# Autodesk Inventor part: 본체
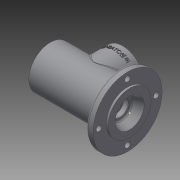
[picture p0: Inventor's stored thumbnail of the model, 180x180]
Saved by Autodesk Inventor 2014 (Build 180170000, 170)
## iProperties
Created: 2016-08
Part Number: 본체
Material: 일반
Document SubType Name: Modeling
Designer: USER
Density: 1 g/cm^3
Appearance: 기본값
Mass: 268.699 g
Surface Area: 614.616 cm^2
Volume: 268.699 cm^3
Author: USER
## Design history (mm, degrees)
sketch "스케치1"
  geometry: 1 further point
sketch "스케치2"
  geometry: L1 (-16.69, 0)-(0, 0); L2 (-115, 0)-(-115, 31); L3 (-115, 31)-(-13, 31); L4 (-13, 31)-(-13, 50); L5 (-13, 50)-(-3, 50); L6 (-3, 50)-(-3, 31); L7 (-3, 31)-(0, 31); L8 (0, 31)-(0, 0); L9 (0, 0)-(-115, 0)
  constraints: 18 end point, 4 parallel, 2 collinear, 2 perpendicular, 1 horizontal, 1 point on line
  dimensions: "d5" = 62 diameter of L3 L1; "d6" = 100 diameter of L5 L1; "d7" = 62 diameter of L7 L1; "d8" = 115 distance between parallel lines of L8 L2; "d9" = 102 distance of L2.end L3.end; "d10" = 10 distance of L4.end L5.end
revolve "회전1" sketch "스케치2" stored, may be unused: angle "d11" = 90 deg
node "작업 평면1"
sketch "스케치3"
  geometry: L1 (115, 31)-(115, -31) reference; C1 r 30 at (59, 0); 1 further point
  constraints: 1 centre point, 1 horizontal alignment
  dimensions: "d13" = 60 diameter of C1; "d14" = 56 distance from line of L1 C1.centre
extrude "돌출1" join sketch "스케치3" stored distance "d15" = 10; taper "d16" = 0 deg
sketch "스케치4" dims "d17" = 48
  geometry: C1 r 30 at (0, 0) reference; 3 further points
  constraints: 2 vertical alignment, 1 coincident, 2 other
hole "구멍1" sketch "스케치4" at (0, 24) diameter "d18" = 3.242; stored, may be unused: countersink angle "d22" = 90 deg, drill point angle "d24" = 118 deg; dims "d19" = 8, "d20" = 4, "d21" = 2, "d23" = 10
sketch "스케치7"
  geometry: C1 r 31 at (0, 0) reference; C2 r 21 at (0, 0)
  constraints: 1 centre point, 1 coincident
  dimensions: "d28" = 42 diameter of C2
extrude "돌출2" cut sketch "스케치7" distance "d29" = 9; taper "d30" = 0 deg
sketch "스케치9"
  geometry: C1 r 21 at (0, 0) reference; C2 r 24 at (0, 0)
  constraints: 1 centre point, 1 coincident
  dimensions: "d32" = 48 diameter of C2
extrude "돌출3" cut sketch "스케치9" distance "d33" = 3; taper "d34" = 0 deg
sketch "스케치10"
  geometry: C1 r 24 at (0, 0) reference; C2 r 20 at (0, 0)
  constraints: 1 centre point, 1 coincident
  dimensions: "d35" = 40 diameter of C2
extrude "돌출4" cut sketch "스케치10" distance "d36" = 9; taper "d37" = 0 deg
feature "스레드1" dims "d62" = 10, "d63" = 0
chamfer "모따기1" distance "d64" = 1; stored, may be unused: second distance "d65" = 2, angle "d66" = 45 deg
fillet "모깎기4" dims "d79" = 3
fillet "모깎기5" dims "d83" = 3
sketch "스케치22" dims "d84" = 83
  geometry: C1 r 50 at (0, 0) reference; C2 r 31 at (0, 0) reference; C3 r 4 at (0, 41.5); 1 further point
  constraints: 2 vertical alignment, 1 centre point, 1 coincident, 2 other
  dimensions: "d85" = 8 diameter of C3
extrude "돌출13" cut sketch "스케치22" distance "d86" = 16.55; taper "d87" = 0 deg
node "작업 평면2"
sketch "스케치24"
  geometry: L1 (-56, -80)-(-56, -18) reference; L2 (-30, 0)-(30, 0) reference; 2 further points
  constraints: 1 other
  dimensions: "d91" = 56 distance from line of point (0, -10) L1; "d92" = 10 distance from line of point (0, -10) L2
feature "엠보싱1" sketch "스케치24" dims "d93" = 0.5, "d94" = 0
sketch "스케치28"
  geometry: C1 r 20 at (0, 0) reference; C2 r 17.5 at (0, 0)
  constraints: 1 centre point, 1 coincident
  dimensions: "d95" = 35 diameter of C2
extrude "돌출14" cut sketch "스케치28" distance "d96" = 3.25; taper "d97" = 0 deg
sketch "스케치29"
  geometry: C1 r 17.5 at (0, 0) reference; C2 r 18.5 at (0, 0)
  constraints: 1 centre point, 1 coincident
  dimensions: "d98" = 37 diameter of C2
extrude "돌출15" cut sketch "스케치29" distance "d99" = 1.75; taper "d100" = 0 deg
sketch "스케치30"
  geometry: C1 r 18.5 at (0, 0) reference; C2 r 17.5 at (0, 0)
  constraints: 1 centre point, 1 coincident
  dimensions: "d101" = 35 diameter of C2
extrude "돌출16" cut sketch "스케치30" distance "d102" = 11; taper "d103" = 0 deg
sketch "스케치31"
  geometry: C1 r 17.5 at (0, 0) reference; C2 r 26 at (0, 0)
  constraints: 1 centre point, 1 coincident
  dimensions: "d104" = 52 diameter of C2
extrude "돌출17" cut sketch "스케치31" distance "d105" = 38; taper "d106" = 0 deg
sketch "스케치32"
  geometry: C1 r 17.5 at (0, 0); 2 further points
  constraints: 1 centre point, 1 coincident, 1 horizontal alignment
  dimensions: "d107" = 35 diameter of C1
extrude "돌출18" cut sketch "스케치32" distance "d108" = 11; taper "d109" = 0 deg
sketch "스케치33"
  geometry: C1 r 17.5 at (0, 0) reference; C2 r 16.5 at (0, 0)
  constraints: 1 centre point, 1 coincident
  dimensions: "d110" = 33 diameter of C2
extrude "돌출19" cut sketch "스케치33" distance "d111" = 5; taper "d112" = 0 deg
sketch "스케치34"
  geometry: C1 r 16.5 at (0, 0) reference; C2 r 10 at (0, 0)
  constraints: 1 centre point, 1 coincident
  dimensions: "d113" = 20 diameter of C2
extrude "돌출20" cut sketch "스케치34" distance "d114" = 2.7; taper "d115" = 0 deg
sketch "스케치35"
  geometry: C1 r 10 at (0, 0) reference; C2 r 12.5 at (0, 0)
  constraints: 1 centre point, 1 coincident
  dimensions: "d116" = 25 diameter of C2
extrude "돌출21" cut sketch "스케치35" distance "d117" = 7.3; taper "d118" = 0 deg
sketch "스케치37"
  geometry: L1 (-14, -12.5)-(-14, 12.5) reference; L2 (0, -31)-(0, 31) reference; L3 (-14, 0)-(-14, 16); L4 (-14, 16)-(0, 21); L5 (0, 21)-(0, 0); L6 (0, 0)-(-14, 0)
  constraints: 8 end point, 2 point on line, 1 collinear, 1 midpoint, 1 perpendicular
  dimensions: "d119" = 16 distance of L3.start L3.end; "d120" = 21 distance of L5.end L4.end
revolve "회전3" sketch "스케치37" stored, may be unused: angle "d121" = 90 deg
chamfer "모따기5" distance "d122" = 1; stored, may be unused: second distance "d123" = 2, angle "d124" = 30 deg
fillet "모깎기6" dims "d125" = 3
fillet "모깎기7" dims "d126" = 0.3
fillet "모깎기8" dims "d127" = 3
fillet "모깎기9" dims "d128" = 0.3
fillet "모깎기10" dims "d129" = 3
chamfer "모따기6" distance "d130" = 0.7; stored, may be unused: second distance "d131" = 2, angle "d132" = 30 deg
sketch "스케치40"
  geometry: C1 r 30 at (0, 0) reference; C2 r 19 at (0, 0); 1 further point
  constraints: 1 centre point, 1 coincident
  dimensions: "d134" = 38 diameter of C2
extrude "돌출22" cut sketch "스케치40" stored distance "d135" = 7.3; taper "d136" = 0 deg
sketch "스케치41"
  geometry: 1 further point
node "솔리드1"
pattern_circular "원형 패턴1" dims angle "d26" = 360 deg
pattern_circular "원형 패턴2" dims angle "d89" = 360 deg
other parameters: "d12" = 49
